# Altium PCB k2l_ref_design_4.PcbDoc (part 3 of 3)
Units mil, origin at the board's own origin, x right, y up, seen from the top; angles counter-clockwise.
Board outline 8000 x 6000 mil, 2 copper layers (Top Layer, Bottom Layer), stack 62 mil thick; 620 components, 466 nets, 2754 pads, 0 vias.
Unrouted connection lines stored in the file: 183.
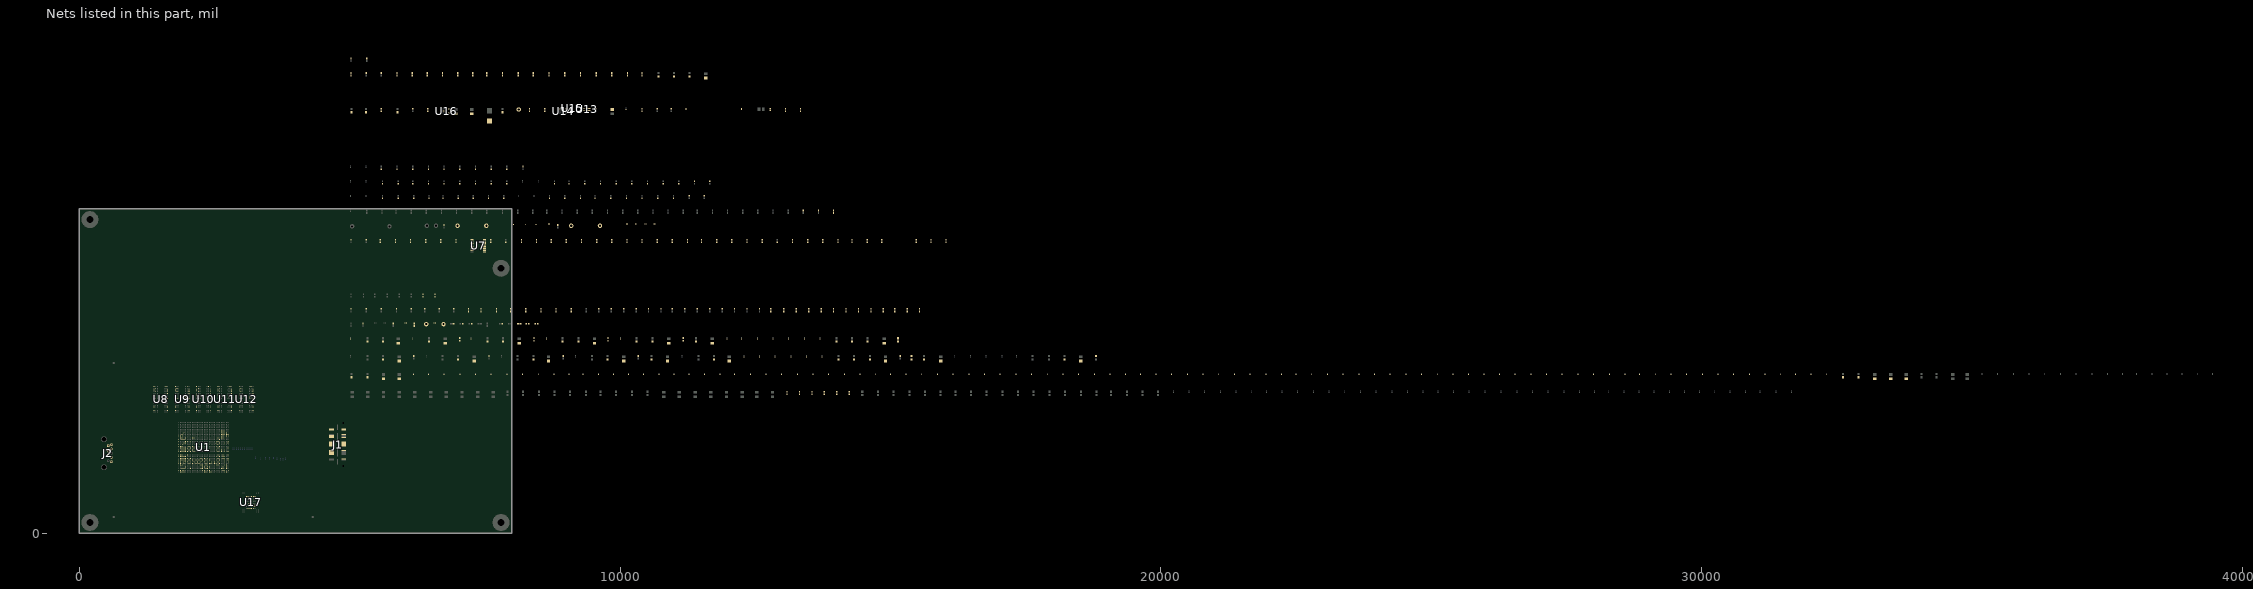
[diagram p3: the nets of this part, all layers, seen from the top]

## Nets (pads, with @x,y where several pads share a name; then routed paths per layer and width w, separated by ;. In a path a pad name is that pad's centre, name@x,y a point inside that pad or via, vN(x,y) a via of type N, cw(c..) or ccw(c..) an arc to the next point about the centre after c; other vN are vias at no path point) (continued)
K2L_DVDD1V8: C435.1 C436.1 C437.1 C438.1 C441.1 C442.1 C451.1 C452.1 C453.1 C454.1 C457.1 C458.1 C461.1 C462.1 C465.1 C466.1 C469.1 C470.1 C503.1 C573.1 C574.1 C575.1 C576.1 L20.2 L21.2 L22.2 L23.2 L24.2 L25.2 L26.2 R71.2 R72.2 R73.2 R74.2 R75.2 R76.2 R77.2 R78.2 R79.2 R80.2 R81.2 R82.2 R83.2 R84.2 R99.2 R100.2 R101.2 R102.2 R103.2 R104.2 R105.2 R106.2 R115.2 R116.2 R117.2 R123.2 R213.2 R215.2 R216.2 U1.AA23 U1.AA25 U1.AA28 U1.AB2 U1.AB6 U1.AB8 U1.AB24 U1.AC7 U1.AC9 U1.AC11 U1.AC23 U1.AC25 U1.AD4 U1.AD6 U1.AD8 U1.AD10 U1.AD24 U1.AD28 U1.AE7 U1.AE9 U1.AE11 U1.AE25 U1.AG5 U1.AH8 U1.AJ1 U1.AJ30 U1.AK2 U1.AK29 U1.J29 U1.K24 U1.L25 U1.M24 U1.N25 U1.N28 U1.P24 U1.R7 U1.R23 U1.R25 U1.T6 U1.T8 U1.T24 U1.U7 U1.U23 U1.U28 U1.V6 U1.V24 U1.W3 U1.W7 U1.W23 U1.W25 U1.Y6 U1.Y24 U7.20 U17.D3 U17.G4 U17.H8 U17.J6
K2L_DVDD1V35: C504.1 C508.1 C509.1 C510.1 C511.1 C512.1 C513.1 C514.1 C515.1 C516.1 C519.1 C520.1 C521.1 C522.1 C523.1 C524.1 C525.1 C526.1 C527.1 C530.1 C531.1 C532.1 C533.1 C534.1 C535.1 C536.1 C537.1 C538.1 C541.1 C542.1 C543.1 C544.1 C545.1 C546.1 C547.1 C548.1 C549.1 C552.1 C553.1 C554.1 C555.1 C556.1 C557.1 C558.1 C559.1 C560.1 U8.A1 U8.A8 U8.B2 U8.C1 U8.C9 U8.D2 U8.D9 U8.E9 U8.F1 U8.G7 U8.H2 U8.H9 U8.K2 U8.K8 U8.N1 U8.N9 U8.R1 U8.R9 U9.A1 U9.A8 U9.B2 U9.C1 U9.C9 U9.D2 U9.D9 U9.E9 U9.F1 U9.G7 U9.H2 U9.H9 U9.K2 U9.K8 U9.N1 U9.N9 U9.R1 U9.R9 U10.A1 U10.A8 U10.B2 U10.C1 U10.C9 U10.D2 U10.D9 U10.E9 U10.F1 U10.G7 U10.H2 U10.H9 U10.K2 U10.K8 U10.N1 U10.N9 U10.R1 U10.R9 U11.A1 U11.A8 U11.B2 U11.C1 U11.C9 U11.D2 U11.D9 U11.E9 U11.F1 U11.G7 U11.H2 U11.H9 U11.K2 U11.K8 U11.N1 U11.N9 U11.R1 U11.R9 U12.A1 U12.A8 U12.B2 U12.C1 U12.C9 U12.D2 U12.D9 U12.E9 U12.F1 U12.G7 U12.H2 U12.H9 U12.K2 U12.K8 U12.N1 U12.N9 U12.R1 U12.R9
K2L_EMIFA11: R217.1 U17.C4
K2L_EMIFA11_RS: R217.2 U1.AD30
K2L_EMIFA12: R218.1 U17.D5
K2L_EMIFA12_RS: R218.2 U1.V28
K2L_EMIFBE0Z: R214.1
K2L_EMIFBE0Z_RS: R214.2 U1.AB30
K2L_EMIFCE0Z: R201.1 U17.C6
K2L_EMIFD00: R202.2 U17.H4
K2L_EMIFD00_RS: R202.1 U1.U26
K2L_EMIFD01: R203.2 U17.J4
K2L_EMIFD01_RS: R203.1 U1.AB28
K2L_EMIFD02: R204.2 U17.K4
K2L_EMIFD02_RS: R204.1 U1.W27
K2L_EMIFD03: R205.2 U17.K5
K2L_EMIFD03_RS: R205.1 U1.AC28
K2L_EMIFD04: R206.2 U17.K6
K2L_EMIFD04_RS: R206.1 U1.Y27
K2L_EMIFD05: R208.2 U17.J7
K2L_EMIFD05_RS: R208.1 U1.AB27
K2L_EMIFD06: R210.2 U17.K7
K2L_EMIFD06_RS: R210.1 U1.AA27
K2L_EMIFD07: R212.2 U17.J8
K2L_EMIFD07_RS: R212.1 U1.V26
K2L_EMIFOEZ: R207.1 U17.D4
K2L_EMIFOEZ_RS: R207.2 U1.T30
K2L_EMIFRNW: R211.1
K2L_EMIFRNW_RS: R211.2 U1.M30
K2L_EMIFWAIT0: R213.1 U1.AC30 U1.Y30 U17.C8
K2L_EMIFWEZ: R209.1 U17.C7
K2L_EMIFWEZ_RS: R209.2 U1.V30
K2L_GPIO0: R106.1 R114.2 U1.G26
K2L_GPIO1: R84.1 R98.2 U1.F27
K2L_GPIO2: R83.1 R97.2 U1.F26
K2L_GPIO3: R82.1 R96.2 U1.G29
K2L_GPIO4: R81.1 R95.2 U1.F28
K2L_GPIO5: R80.1 R94.2 U1.G27
K2L_GPIO6: R79.1 R93.2 U1.H30
K2L_GPIO7: R78.1 R92.2 U1.J26
K2L_GPIO8: R77.1 R91.2 U1.H26
K2L_GPIO9: R76.1 R90.2 U1.H29
K2L_GPIO10: R75.1 R89.2 U1.J27
K2L_GPIO11: R74.1 R88.2 U1.H28
K2L_GPIO12: R73.1 R87.2 U1.G28
K2L_GPIO13: R72.1 R86.2 U1.H27
K2L_GPIO14: R105.1 R113.2 U1.J30
K2L_GPIO15: R104.1 R112.2 U1.K27
K2L_GPIO16: R103.1 R111.2 U1.K26
K2L_GPIO17: U1.W2
K2L_GPIO18: U1.Y1
K2L_GPIO19: U1.V3
K2L_GPIO20: U1.W1
K2L_GPIO21: U1.V1
K2L_GPIO22: U1.V2
K2L_GPIO23: U1.U4
K2L_GPIO24: U1.V5
K2L_GPIO26: U1.V4
K2L_GPIO27: U1.U1
K2L_GPIO28: U1.T3
K2L_GPIO29: U1.U3
K2L_GPIO30: U1.T5
K2L_GPIO31: U1.U5
K2L_GPIO32: U1.T4
K2L_JESD_RXN0: C6.2
K2L_JESD_RXN0_CAP: C6.1 U1.AJ19
K2L_JESD_RXN1: C8.2
K2L_JESD_RXN1_CAP: C8.1 U1.AK20
K2L_JESD_RXN2: C10.2
K2L_JESD_RXN2_CAP: C10.1 U1.AJ16
K2L_JESD_RXN3: C12.2
K2L_JESD_RXN3_CAP: C12.1 U1.AK17
K2L_JESD_RXP0: C5.2
K2L_JESD_RXP0_CAP: C5.1 U1.AJ18
K2L_JESD_RXP1: C7.2
K2L_JESD_RXP1_CAP: C7.1 U1.AK19
K2L_JESD_RXP2: C9.2
K2L_JESD_RXP2_CAP: C9.1 U1.AJ15
K2L_JESD_RXP3: C11.2
K2L_JESD_RXP3_CAP: C11.1 U1.AK16
K2L_JESD_SERDES0_REFCLKN: JESDCLK2.1 U1.AF18
K2L_JESD_SERDES0_REFCLKP: JESDCLK1.1 U1.AF17
K2L_JESD_SERDES1_REFCLKN: JESDCLK4.1 U1.AF15
K2L_JESD_SERDES1_REFCLKP: JESDCLK3.1 U1.AF14
K2L_JESD_TXN0: U1.AH17
K2L_JESD_TXN1: U1.AG18
K2L_JESD_TXN2: U1.AH14
K2L_JESD_TXN3: U1.AG15
K2L_JESD_TXP0: U1.AH18
K2L_JESD_TXP1: U1.AG19
K2L_JESD_TXP2: U1.AH15
K2L_JESD_TXP3: U1.AG16
K2L_LRESETNMIENZ: R3.1 U1.AF2
K2L_LRESETZ: R1.1 U1.AK3
K2L_MIPI_DETECTZ: J1.58 R123.1
K2L_MIPI_EMU00: J1.19 R124.1
K2L_MIPI_EMU00_RS: R124.2 U1.AC3
K2L_MIPI_EMU01: J1.21 R125.1
K2L_MIPI_EMU01_RS: R125.2 U1.AD5
K2L_MIPI_EMU02: J1.13 R127.1
K2L_MIPI_EMU02_RS: R127.2 U1.AD1
K2L_MIPI_EMU03: J1.17 R128.1
K2L_MIPI_EMU03_RS: R128.2 U1.AD2
K2L_MIPI_EMU04: J1.23 R129.1
K2L_MIPI_EMU04_RS: R129.2 U1.AE1
K2L_MIPI_EMU05: J1.25 R130.1
K2L_MIPI_EMU05_RS: R130.2 U1.AC4
K2L_MIPI_EMU06: J1.27 R131.1
K2L_MIPI_EMU06_RS: R131.2 U1.AC5
K2L_MIPI_EMU07: J1.29 R132.1
K2L_MIPI_EMU07_RS: R132.2 U1.AC2
K2L_MIPI_EMU08: J1.31 R133.1
K2L_MIPI_EMU08_RS: R133.2 U1.AC1
K2L_MIPI_EMU09: J1.33 R134.1
K2L_MIPI_EMU09_RS: R134.2 U1.AB4
K2L_MIPI_EMU10: J1.35 R135.1
K2L_MIPI_EMU10_RS: R135.2 U1.AB5
K2L_MIPI_EMU11: J1.37 R136.1
K2L_MIPI_EMU11_RS: R136.2 U1.AB3
K2L_MIPI_EMU12: J1.39 R137.1
K2L_MIPI_EMU12_RS: R137.2 U1.AA1
K2L_MIPI_EMU13: J1.41 R138.1
K2L_MIPI_EMU13_RS: R138.2 U1.AA4
K2L_MIPI_EMU14: J1.43 R139.1
K2L_MIPI_EMU14_RS: R139.2 U1.AA2
K2L_MIPI_EMU15: J1.45 R140.1
K2L_MIPI_EMU15_RS: R140.2 U1.AA3
K2L_MIPI_EMU16: J1.47 R141.1
K2L_MIPI_EMU16_RS: R141.2 U1.AA5
K2L_MIPI_EMU17: J1.49 R142.1
K2L_MIPI_EMU17_RS: R142.2 U1.Y3
K2L_MIPI_EMU18: J1.51 R143.1
K2L_MIPI_EMU18_RS: R143.2 U1.Y2
K2L_MIPI_EMU19: J1.53
K2L_MIPI_EMU20: J1.55
K2L_MIPI_EMU21: J1.18
K2L_MIPI_EMU22: J1.20
K2L_MIPI_EMU23: J1.22
K2L_MIPI_EMU24: J1.24
K2L_MIPI_EMU25: J1.26
K2L_MIPI_EMU26: J1.28
K2L_MIPI_EMU27: J1.30
K2L_MIPI_EMU28: J1.32
K2L_MIPI_EMU29: J1.34
K2L_MIPI_EMU30: J1.36
K2L_MIPI_EMU31: J1.38
K2L_MIPI_EMU32: J1.40
K2L_MIPI_EMU33: J1.42
K2L_MIPI_TCK: R148.2 U1.AJ3
K2L_MIPI_TCK_BUFF: R119.1 U7.11 U7.13
K2L_MIPI_TCK_BUFF_RS: J1.3 R119.2
K2L_MIPI_TCK_RS: R148.1 U7.9
K2L_MIPI_TCKR_BUFF: J1.7 R149.2
K2L_MIPI_TCKR_BUFF_RS: R149.1 U7.7
K2L_MIPI_TDI: R147.2 U1.AJ4
K2L_MIPI_TDI_BUFF: R120.1 U7.8
K2L_MIPI_TDI_BUFF_RS: J1.5 R120.2
K2L_MIPI_TDI_RS: R147.1 U7.12
K2L_MIPI_TDO: J1.4 R146.2
K2L_MIPI_TDO_BUFF: R122.1 U7.6
K2L_MIPI_TDO_BUFF_RS: R122.2 U1.AH4
K2L_MIPI_TDO_RS: R146.1 U7.14
K2L_MIPI_TGTDETECTZ: J1.15 R126.1
K2L_MIPI_TGTRSTZ: J1.6 R115.1
K2L_MIPI_TMS: R145.2 U1.AH3
K2L_MIPI_TMS_BUFF: R118.2 U7.4
K2L_MIPI_TMS_BUFF_RS: J1.2 R118.1
K2L_MIPI_TMS_RS: R145.1 U7.16
K2L_MIPI_TRSTZ: R144.2 U1.AK4
K2L_MIPI_TRSTZ_BUFF: R121.2 U7.2
K2L_MIPI_TRSTZ_BUFF_RS: J1.8 R121.1
K2L_MIPI_TRSTZ_RS: R144.1 U7.18
K2L_MIPI_VREF_JTAG: J1.1 R116.1
K2L_NMIZ: R2.1 U1.AJ2
K2L_PCIECLKN: U1.AE20
K2L_PCIECLKP: U1.AE19
K2L_PLLLOCK: K1.1 R12.2 U1.AH29
K2L_PORZ: R6.2 U1.G4
K2L_RESETFULLZ: R7.2 U1.AE2
K2L_RESETSTATZ: R4.2 U1.AE4
K2L_RESETZ: R8.2 U1.AF3
K2L_SCL1: R16.1 U1.L3
K2L_SDA1: R15.1 U1.M5
K2L_SERDES0_REF: R23.2 U1.AE17
K2L_SERDES1_REF: R24.2 U1.AE13
K2L_SGMIICLKN: U1.AF24
K2L_SGMIICLKP: U1.AF23
K2L_SYSCLKN: C2.2
K2L_SYSCLKN_CS: C2.1 U1.AG29
K2L_SYSCLKOUT: K2.1 R11.2
K2L_SYSCLKOUT_RS: R11.1 U1.AF28
K2L_SYSCLKP: C1.2
K2L_SYSCLKP_CS: C1.1 U1.AF29
K2L_TIMI0: R100.1 R108.2 U1.J2
K2L_TIMI1: R99.1 R107.2 U1.J1
K2L_TIMO0: R102.1 R110.2 U1.H3
K2L_TIMO1: R101.1 R109.2 U1.J3
K2L_UART0_CTS: U1.L4
K2L_UART0_RTS: U1.K2
K2L_UART0_RXD: U1.K5
K2L_UART0_TXD: U1.K3
K2L_USBCLKN: 
K2L_USBCLKP: 
K2L_USBCLKP_CS: R188.1 R189.1 R190.1 R190.2 R191.2 R192.2 U1.P3 U1.R3
K2L_USBDM: J2.2 U1.R1 U13.2 U13.13
K2L_USBDP: J2.3 U1.P1 U13.1 U13.14
K2L_USBDRVVBUS: R198.1 U1.M6
K2L_USBDRVVBUS_INVOUT: R196.1 R200.2 U14.4 U16.4
K2L_USBDRVVBUS_RS: R198.2 R200.1 U16.2
K2L_USBRXM: J2.5 U1.T2 U13.6 U13.9
K2L_USBRXP: J2.6 U1.R2 U13.7 U13.8
K2L_USBTXM: C563.2 U1.M1
K2L_USBTXM_CS: C563.1 J2.8 U13.3 U13.12
K2L_USBTXP: C564.2 U1.L1
K2L_USBTXP_CS: C564.1 J2.9 U13.4 U13.11
K2L_USBVBUS: C566.1 R193.1 U15.A1
K2L_USBVBUS_EN: R199.2 U15.B2
K2L_USBVBUS_RS: C565.1 R193.2 U1.N4
K2L_VCNTL0: R70.1 U1.AJ27
K2L_VCNTL1: R69.1 U1.AK28
K2L_VCNTL2: R68.1 U1.AJ28
K2L_VCNTL3: R67.1 U1.AG27
K2L_VCNTL4_VCL: R66.1 U1.AH27
K2L_VCNTL5_VD: R65.1 U1.AH26
K2L_VDDAHV_1V8_FILT: C443.1 C444.1 C445.1 C446.1 C447.1 C448.1 C449.1 C450.1 L22.1 U1.AD12 U1.AD14 U1.AD16 U1.AD18 U1.AD20 U1.AD22
K2L_VDDALV_FILT: C471.1 C472.1 C473.1 C474.1 C475.1 C476.1 C477.1 C478.1 C479.1 L27.1 U1.AB14 U1.AB16 U1.AB18 U1.AC13 U1.AC15 U1.AC17 U1.AC19
K2L_VDDCMON: U1.K10
K2L_VDDTMON: U1.N23
K2L_VDDUSB: C492.1 C493.1 L30.1 U1.U9
K2L_VP_FILT: C484.1 C485.1 L28.1 U1.V8
K2L_VPH_FILT: C499.1 C500.1 L31.1 U1.T10
K2L_VPTX_FILT: C488.1 C489.1 L29.1 U1.V10
K2L_VSSCMON: U1.K9
K2L_VSSTMON: U1.M23
MCU_NAND_WP_EN#: R216.1 R220.2 U17.C3
MIPI_VREF_EMU: J1.12 R117.1
NAND_LOCKPRE: R215.1 R219.2 U17.G5
NetC504_2: C504.2 R152.2 R153.2
NetR150_2: R150.2 U7.15 U7.17
NetR151_2: R151.2 U7.1 U7.19
NetR194_2: R194.2 U1.N5
NetR195_2: R195.2 U1.M8
NetR197_1: R197.1 U14.5
NetR201_2: R201.2 U1.N30
NetR221_2: R221.2 U1.AE23
NetR222_2: R222.2 U1.AE22
SDRAM_RZQ0: R183.2 R185.2 R186.2 R187.2 U8.L8 U10.L8 U11.L8 U12.L8
SDRAM_RZQ1: R184.2 U9.L8
USB_VBUS: C570.1
USB_VBUS_5V0: C567.1 C568.1 C569.1 J2.1 K15.1 U14.1 U15.A2
VSYS_DVDD0V85: C480.1 C481.1 C482.1 C483.1 C486.1 C487.1 C490.1 C491.1 C494.1 C495.1 L27.2 L28.2 L29.2 L30.2 R188.2 R189.2
VSYS_DVDD1V8: C324.1 C325.1 C326.1 C327.1 C328.1 C329.1 C330.1 C331.1 C332.1 C333.1 C334.1 C335.1 C336.1 C337.1 C338.1 C339.1 C340.1 C341.1 C342.1 C343.1 C344.1 C345.1 C346.1 C347.1 C348.1 C349.1 C350.1 C351.1 C352.1 C353.1 C354.1 C355.1 C356.1 C357.1 C358.1 C359.1 C360.1 C361.1 C362.1 C363.1 C364.1 C365.1 C366.1 C367.1 C368.1 C369.1 C370.1 C371.1 C372.1 C373.1 C374.1 C375.1 C376.1 C377.1 C378.1 C379.1 C380.1 R1.2 R2.2 R3.2 R13.2 R15.2 R16.2 R65.2 R66.2 R67.2 R68.2 R69.2 R70.2 U16.5
VSYS_DVDD1V35: C381.1 C382.1 C383.1 C384.1 C385.1 C386.1 C387.1 C388.1 C389.1 C390.1 C391.1 C392.1 C393.1 C394.1 C395.1 C396.1 C397.1 C398.1 C399.1 C400.1 C401.1 C402.1 C403.1 C404.1 C405.1 C406.1 C407.1 C408.1 C409.1 C410.1 C411.1 C412.1 C413.1 C414.1 C415.1 C416.1 C417.1 C418.1 C419.1 C420.1 C424.1 C425.1 C426.1 C427.1
VSYS_DVDD3V3: C496.1 C497.1 C498.1 C501.1 C502.1 L31.2 U1.R9
VSYS_DVDD5V0: C571.1 C572.1 R196.2 R197.2
pads on no net: FID1.1 FID2.1 FID3.1 H1.1 H2.1 H3.1 H4.1 J1.9 J1.10 J1.11 J1.14 J1.44 J1.46 J1.48 J1.50 J1.52 J1.54 J1.56 J1.59 J1.60 J1.MH1 J1.MH2 U1.A11 U1.AA26 U1.AA30 U1.AB26 U1.AB29 U1.AC26 U1.AC27 U1.AC29 U1.AD26 U1.AD27 U1.AE3 U1.AE15 U1.AE21 U1.AE28 U1.AE29 U1.AF1 U1.AF4 U1.AF5 U1.AF6 U1.AF8 U1.AF20 U1.AF22 U1.AG1 U1.AG2 U1.AH1 U1.AH2 U1.AH28 U1.AJ12 U1.AJ13 U1.AJ29 U1.AK13 U1.AK14 U1.B14 U1.B15 U1.C12 U1.E13 U1.F1 U1.F2 U1.F3 U1.F11 U1.F14 U1.F17 U1.G2 U1.H1 U1.H25 U1.J4 U1.J5 U1.J25 U1.K4 U1.K28 U1.K29 U1.K30 U1.L5 U1.L28 U1.M2 U1.M3 U1.M4 U1.M27 U1.M29 U1.N2 U1.P26 U1.P27 U1.P28 U1.P29 U1.P30 U1.R26 U1.R27 U1.R28 U1.R29 U1.R30 U1.T26 U1.T27 U1.T28 U1.T29 U1.U27 U1.U30 U1.V27 U1.V29 U1.W5 U1.W26 U1.W28 U1.W29 U1.W30 U1.Y4 U1.Y26 U1.Y28 U1.Y29 U7.3 U7.5 U8.J1 U8.J9 U8.L1 U8.L9 U8.M7 U9.J1 U9.J9 U9.L1 U9.L9 U9.M7 U10.J1 U10.J9 U10.L1 U10.L9 U10.M7 U11.J1 U11.J9 U11.L1 U11.L9 U11.M7 U12.A2 U12.A3 U12.A7 U12.B7 U12.B8 U12.C2 U12.C3 U12.C7 U12.C8 U12.D3 U12.D7 U12.J1 U12.J9 U12.L1 U12.L9 U12.M7 U14.3 U16.1 U17.A1 U17.A2 U17.A9 U17.A10 U17.B1 U17.B9 U17.B10 U17.D6 U17.D7 U17.D8 U17.E3 U17.E4 U17.E5 U17.E6 U17.E7 U17.E8 U17.F3 U17.F4 U17.F5 U17.F6 U17.F8 U17.G3 U17.G6 U17.G7 U17.G8 U17.H3 U17.H5 U17.H6 U17.H7 U17.J3 U17.J5 U17.L1 U17.L2 U17.L9 U17.L10 U17.M1 U17.M2 U17.M9 U17.M10

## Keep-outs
Keep-Out Layer:
  text ".Layer_Name" at 577,-858.49 h60

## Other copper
Top Layer:
  text ".Layer_Name" at 577,-858.49 h60
Bottom Layer:
  text ".Layer_Name" at 577,-858.49 h60

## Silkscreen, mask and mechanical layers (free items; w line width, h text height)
Top Overlay:
  region: 2680,210 2380,210 2380,110 2680,110
  text "'.PRJ_Number'.PCB_Rev-" at 1720.47,118.11 h108.27
  text ".Layer_Name" at 577,-858.49 h60
Bottom Overlay:
  text ".Layer_Name" at 577,-858.49 h60
Top Paste:
  text ".Layer_Name" at 577,-858.49 h60
Bottom Paste:
  text ".Layer_Name" at 577,-858.49 h60
Top Solder:
  text ".Layer_Name" at 577,-858.49 h60
  text ".Layer_Name" at 577,-858.49 h60
Bottom Solder:
  text ".Layer_Name" at 577,-858.49 h60
Drill Guide:
  text ".Layer_Name" at 577,-858.49 h60
M1 Board Outline:
  the board outline again, w10
  text ".Layer_Name" at 577,-858.49 h60
M2 Board Dimensions:
  rectangle: 0,-275 125,-150
  rectangle: 125,-400 500,-275
  lines w7: 0,-275 1000,-275 ; 125,-400 125,-150 ; 250,-400 250,-150 ; 500,-400 500,-150 ; 750,-400 750,-150 ; 0,-400 1000,-400 1000,-150 0,-150 0,-400
  text ".Layer_Name" at 577,-858.49 h60
M3 3D STEP Top:
  text ".Layer_Name" at 577,-858.49 h60
M4 3D STEP Bottom:
  text ".Layer_Name" at 577,-858.49 h60
M5 Assembly Top:
  lines w10: -292,-930.17 6308,-930.17 ; -292,-726.83 6310,-726.83 ; -292,-523.5 -292,-1133.5 3713,-1133.5 6310,-1133.5 6310,-523.5 -291.5,-523.5 -291.5,-1133.5 1284,-1133.5 ; 2173,-1133.5 2173,-523.5 ; 3440,-726.83 3440,-523.5 ; 4280,-726.83 4280,-523.5 ; 4902,-1140 4902,-937.17
  text "COMPONENTS MARKED 'DNP' SHOULD NOT BE POPULATED." at 1153.5,-318.5 h60
  text "ASSEMBLY VARIANT:" at 1153,-434 h60
  text ".VariantName" at 2189,-434 h60
  text "PCB VIEWED FROM TOP SIDE" at -228.5,-655.67 h60
  text "BOARD #:" at 2248,-655.67 h60
  text ".PRJ_Number" at 2793.5,-655.67 h60
  text "REV:" at 3638,-655.67 h60
  text ".PCB_Rev" at 3929.5,-655.67 h60
  text "SVN REV:" at 4476,-655.67 h60
  text ".VersionControl_RevNumber" at 4982,-655.67 h60
  text "TID #:" at 2248,-859 h60
  text ".TID" at 2793.5,-859 h60
  text "PLOT NAME =" at -228.5,-1064.34 h60
  text ".plot_File_Name" at 577,-1064.34 h60
  text "GENERATED    :" at 2250,-1064.34 h60
  text ".Print_Date" at 3119.5,-1064.34 h60
  text ".Print_Time" at 3848.5,-1064.34 h60
  text "TEXAS INSTRUMENTS" at 5113,-1064.34 h60
M6 Assembly Bottom:
  lines w10: -292.5,-727.33 6309.5,-727.33 ; -290.5,-930.67 6309.5,-930.67 ; 1115.5,-1140.5 1115.5,-937.67 ; 1737.5,-727.33 1737.5,-524 ; 2577.5,-727.33 2577.5,-524 ; 3844.5,-1134 3844.5,-524 ; 4733.5,-1134 6309,-1134 6309,-524 -292.5,-524 -292.5,-1134 2304.5,-1134 6309.5,-1134 6309.5,-524
  text "COMPONENTS MARKED 'DNP' SHOULD NOT BE POPULATED." at 6102,-318 h60
  text ".VariantName" at 5058,-434 h60
  text "ASSEMBLY VARIANT:" at 6097,-434 h60
  text ".VersionControl_RevNumber" at 1035.5,-656.17 h60
  text "SVN REV:" at 1541.5,-656.17 h60
  text ".PCB_Rev" at 2088,-656.17 h60
  text "REV:" at 2379.5,-656.17 h60
  text ".PRJ_Number" at 3224,-656.17 h60
  text "BOARD #:" at 3769.5,-656.17 h60
  text "PCB VIEWED FROM BOTTOM SIDE" at 6246,-656.17 h60
  text ".TID" at 3224,-859.5 h60
  text "TID #:" at 3769.5,-859.5 h60
  text "TEXAS INSTRUMENTS" at 904.5,-1064.84 h60
  text ".Print_Time" at 2169,-1064.84 h60
  text ".Print_Date" at 2898,-1064.84 h60
  text "GENERATED    :" at 3767.5,-1064.84 h60
  text ".plot_File_Name" at 5440.5,-1064.84 h60
  text "PLOT NAME =" at 6246,-1064.84 h60
M9 Title Sheet:
  drawing of 57 lines, arcs and shapes, not listed
  text "1" at 739.84,8036.5 h70
  text "2" at 3235.5,8036.5 h70
  text "3" at 5724.84,8036.5 h70
  text "4" at 8231.51,8036.5 h70
  text "5" at 10730.5,8036.5 h70
  text "6" at 13235.5,8036.5 h70
  text "A" at -416.5,6893.5 h70
  text "A" at 14383.5,6893.5 h70
  text "B" at -416.5,4513.5 h70
  text "B" at 14383.5,4513.5 h70
  text "C" at -416.5,2138.5 h70
  text "C" at 14383.5,2138.5 h70
  text "PROJECT TITLE:" at 11343.5,277.5 h45
  text ".PRJ_Title" at 11393.5,144.17 h70
  text "DESIGNED FOR:" at 11343.5,-23.5 h45
  text ".PRJ_Customer" at 11393.5,-163.5 h70
  text "D" at -416.5,-231.5 h70
  text "D" at 14383.5,-231.5 h70
  text "FILE NAME:" at 11343.5,-323.5 h45
  text ".PCB_File_Name_No_Path" at 11393.5,-443.5 h70
  text "Texas Instruments (TI) and/or its licensors do not warrant the accuracy or completeness of this specification" at 6374,-605.34 h45
  text "ENGINEER:" at 11343.5,-613.5 h45
  text "LAYOUT BY:" at 12848.5,-613.5 h45
  text "or any information contained therein. TI and/or its licensors do not warrant that this design will meet" at 6329.01,-718 h45
  text ".PRJ_Engineer" at 11393.5,-768.49 h70
  text ".PCB_Layout" at 12899,-768.49 h70
  text "the specifications, will be suitable for your application or fit for any particular purpose, or will operate in" at 6329.01,-830.67 h45
  text ".Layer_Name" at 577,-858.49 h60
  text "ALTIUM DESIGNER VERSION:" at 12848.5,-923.5 h45
  text "an implementation. TI and/or its licensors do not warrant that the design is production worthy. You should" at 6329.01,-943.33 h45
  text "completely validate and test your design implementation to confirm the system functionality for your application." at 6374,-1056 h45
  text ".print_Scale" at 11393.5,-1056.83 h70
  text ".Application_BuildNumber" at 12899,-1056.83 h70
  text "1" at 739.84,-1263.5 h70
  text "2" at 3235.5,-1263.5 h70
  text "3" at 5724.84,-1263.5 h70
  text "4" at 8231.51,-1263.5 h70
  text "5" at 10730.5,-1263.5 h70
  text "6" at 13235.5,-1263.5 h70
M10 Fab Notes:
  drawing of 173 lines, arcs and shapes, not listed
  text "DESIGN INFORMATION" at 12378.02,6201 h60
  text "MIN. TRACK WIDTH:" at 11733.46,6021 h60
  text "8" at 12829.7,6021 h60
  text "MIL" at 12984.46,6021 h60
  text "MIN. CLEARANCE:" at 11733.46,5889 h60
  text "0.2" at 12769.7,5889 h60
  text "mm" at 12984.46,5889 h60
  text "MIN. VIA PAD SIZE:" at 11733.46,5757 h60
  text "24" at 12799.71,5757 h60
  text "MIL" at 12984.46,5757 h60
  text "0.05mm (2MIL)" at 12428.46,5615.29 h60
  text "MINIMUM ANNULAR RING" at 11404.23,5611 h60
  text "EXTERNAL" at 13136.46,5611 h60
  text "PER" at 11604.23,5493 h60
  text "IPC-D-275 CLASS 2 LEVEL C" at 11824.23,5493 h60
  text "MIL, HOLES" at 13312.46,5380.71 h60
  text "+/-" at 12920,5380 h60
  text "+/-" at 13774,5380 h60
  text "REGISTRATION TOLERANCES:" at 11404.23,5375 h60
  text "METAL" at 12604,5375 h60
  text "5" at 13180.2,5375 h60
  text "3" at 14013.2,5375 h60
  text "MIL" at 14129.46,5375 h60
  text "+/-" at 13774,5262 h60
  text "HOLE SIZE TOLERANCE (UNLESS OTHERWISE SPECIFIED):" at 11404.23,5257 h60
  text "3" at 14013.2,5257 h60
  text "MIL" at 14129.46,5257 h60
  text "MATERIAL:" at 11329.46,5047.54 h60
  text "FR-4 High Tg" at 12315.9,4907.21 h60
  text "FR-408" at 11750.46,4898.64 h60
  text "OTHER" at 13238.46,4898.64 h60
  text "X" at 12161,4895 h60
  text "62 MIL (1.6mm) +/-10%" at 12070.56,4735.92 h60
  text "THICKNESS:" at 11404.23,4731.64 h60
  text "X" at 11942.4,4731.64 h60
  text "OTHER" at 13355.46,4731.64 h60
  text "TOLERANCE:" at 11404.23,4573.64 h60
  text "X" at 12243.53,4573.64 h60
  text "ANSI IPC-6012 TYPE 3 CLASS 2" at 12430.48,4573.64 h60
  text "OTHER +/-" at 12430.46,4417.64 h60
  text "BOW & TWIST:" at 11404.23,4260.64 h60
  text "X" at 12243.53,4260.64 h60
  text "ANSI IPC-6012 TYPE 3 CLASS 2" at 12430.48,4260.64 h60
  text "OTHER +/-" at 12430.46,4102.13 h60
  text "DRILLING:" at 11329.46,3963.64 h60
  text "REFERENCE:" at 11404.23,3846.64 h60
  text "X" at 12052.46,3846.64 h60
  text "AS SHOWN" at 12239.46,3846.64 h60
  text "X" at 12953.46,3846.64 h60
  text "NC_DRILL FILES" at 13090.46,3846.64 h60
  text "PTH COPPER THICKNESS:" at 11404.23,3688.64 h60
  text "X" at 12534.46,3688.64 h60
  text "20-30 um" at 12671.46,3688.64 h60
  text "OTHER" at 13388.46,3688.64 h60
  text "BOARD FINISH:" at 11329.46,3529.64 h60
  text "SILKSCREEN:" at 11484.68,3411.64 h60
  text "X" at 12433.46,3411.64 h60
  text "TOP" at 12559.46,3411.64 h60
  text "X" at 12943.46,3411.64 h60
  text "BOTTOM" at 13070.46,3411.64 h60
  text "SILKSCREEN COLOR:" at 11484.68,3244.64 h60
  text "X" at 12432.42,3244.64 h60
  text "WHITE" at 12559.46,3244.64 h60
  text "OTHER" at 13070.46,3244.64 h60
  text "X" at 12563.42,3085.44 h60
  text "GREEN" at 12690.46,3085.44 h60
  text "OTHER" at 13308.46,3085.44 h60
  text "SOLDER RESIST COLOR:" at 11484.68,3074.64 h60
  text "X" at 12563.42,2915.44 h60
  text "MATTE" at 12690.46,2915.44 h60
  text "SEMI-GLOSS" at 13308,2914.8 h60
  text "IMMERSION GOLD (ENIG)" at 12390.46,2726.92 h60
  text "ENEPIG" at 13728,2723.64 h60
  text "SURFACE FINISH:" at 11329.46,2722.64 h60
  text "X" at 12203.51,2722.64 h60
  text "IMM. TIN/SILVER OR EQUIV" at 11659,2565.64 h60
  text "OTHER" at 13090.46,2565.64 h60
  text "ARRAY/PANEL:" at 11329.46,2386.64 h60
  text "CUT AND TRIM PER M1 BOARD OUTLINE" at 12390.46,2382.35 h60
  text "N.C. ROUTE" at 12390.46,2230.64 h60
  text "X" at 13069.46,2230.64 h60
  text "V. SCORE" at 13256.46,2230.64 h60
  text "CERTIFICATION:" at 11329.46,2093.64 h60
  text "MATERIALS AND WORKMANSHIP FOR ALL PCBS" at 12054.46,2093.64 h60
  text "TO MEET OR EXCEED THE REQUIREMENTS OF:" at 12054.46,1995.64 h60
  text "X" at 11680.96,1859.13 h60
  text "ANSI IPC-A-600F CLASS ->" at 11819.96,1859.13 h60
  text "X" at 13459.02,1859.13 h60
  text "2" at 13577.96,1859.14 h60
  text "1" at 13262.96,1857.64 h60
  text "3" at 13931.96,1857.64 h60
  text "X" at 12495.02,1699.64 h60
  text "RoHS" at 12631.96,1699.64 h60
  text "OTHER" at 13276.36,1699.64 h60
  text "PER ORDER" at 13673.42,1699.64 h60
  text "ALL BOARDS MUST MEET OR EXCEED UL94-V0 REQUIREMENTS." at 11357,1534 h60
  text "PCB MUST BEAR THE UL94V-0 UL REGISTERED MATERIAL ID NUMBER" at 11357,1414 h60
  text "ADDITIONAL REQUIREMENTS:" at 11329.46,1240.64 h60
  text "MICROSECTION:" at 11404.23,1125.64 h60
  text "YES" at 12309.96,1125.64 h60
  text "REQUIRED" at 13171.46,969.49 h60
  text "BARE BOARD ELEC. TEST:" at 11404.23,966.64 h60
  text "NONE" at 12709.96,966.64 h60
  text "X" at 13044.46,966.64 h60
  text "PER ORDER" at 13763.46,966.64 h60
  text ".Layer_Name" at 577,-858.49 h60
M11 Gerber Information:
  lines w10: -292,-930.17 6308,-930.17 ; -292,-726.83 6310,-726.83 ; -292,-523.5 -292,-1133.5 3713,-1133.5 6310,-1133.5 6310,-523.5 -291.5,-523.5 -291.5,-1133.5 1284,-1133.5 ; 2173,-1133.5 2173,-523.5 ; 3440,-726.83 3440,-523.5 ; 4280,-726.83 4280,-523.5 ; 4902,-1140 4902,-937.17
  text "ALL ARTWORK VIEWED FROM TOP SIDE" at -228.5,-655.67 h60
  text "BOARD #:" at 2248,-655.67 h60
  text ".PRJ_Number" at 2793.5,-655.67 h60
  text "REV:" at 3638,-655.67 h60
  text ".PCB_Rev" at 3929.5,-655.67 h60
  text "SVN REV:" at 4476,-655.67 h60
  text ".VersionControl_RevNumber" at 4982,-655.67 h60
  text "LAYER NAME =" at -228.5,-858.49 h60
  text "TID #:" at 2248,-859 h60
  text ".TID" at 2793.5,-859 h60
  text "PLOT NAME =" at -228.5,-1064.34 h60
  text ".plot_File_Name" at 577,-1064.34 h60
  text "GENERATED    :" at 2250,-1064.34 h60
  text ".Print_Date" at 3119.5,-1064.34 h60
  text ".Print_Time" at 3848.5,-1064.34 h60
  text "TEXAS INSTRUMENTS" at 5113,-1064.34 h60
M12 Stackup:
  drawing of 191 lines, arcs and shapes, not listed
  text "Layer" at 9790.34,7830 h60
  text "Name" at 10200.26,7830 h60
  text "Material" at 11130,7830 h60
  text "Thickness" at 11989.77,7830 h60
  text "Constant" at 12639.6,7830 h60
  text "Board Layer Stack" at 13209.46,7830 h60
  text "1" at 9790.34,7710 h60
  text "Top Overlay" at 10200.26,7710 h60
  text "2" at 9790.34,7590 h60
  text "Top Solder" at 10200.26,7590 h60
  text "Solder Resist" at 11130,7590 h60
  text "0.40mil" at 11989.77,7590 h60
  text "3.5" at 12639.6,7590 h60
  text "3" at 9790.34,7470 h60
  text "Top Layer" at 10200.26,7470 h60
  text "Copper" at 11130,7470 h60
  text "1.40mil" at 11989.77,7470 h60
  text "4" at 9790.34,7350 h60
  text "Dielectric1" at 10200.26,7350 h60
  text "FR-4" at 11130,7350 h60
  text "59.20mil" at 11989.77,7350 h60
  text "4.8" at 12639.6,7350 h60
  text "5" at 9790.34,7230 h60
  text "Bottom Layer" at 10200.26,7230 h60
  text "Copper" at 11130,7230 h60
  text "1.40mil" at 11989.77,7230 h60
  text "6" at 9790.34,7110 h60
  text "Bottom Solder" at 10200.26,7110 h60
  text "Solder Resist" at 11130,7110 h60
  text "0.40mil" at 11989.77,7110 h60
  text "3.5" at 12639.6,7110 h60
  text "7" at 9790.34,6990 h60
  text "Bottom Overlay" at 10200.26,6990 h60
  text ".Layer_Name" at 577,-858.49 h60
M13 Component Bodies Top:
  text ".Layer_Name" at 577,-858.49 h60
M14 Component Bodies Bottom:
  text ".Layer_Name" at 577,-858.49 h60
M15 Courtyards Top:
  text ".Layer_Name" at 577,-858.49 h60
M16 Courtyards Bottom:
  text ".Layer_Name" at 577,-858.49 h60
Drill Drawing:
  circle w10: c7923.12,5632.03 r27.63
  lines w10: 7895.5,5783.97 7950.75,5783.97 7923.12,5728.72 7895.5,5783.97 ; 7895.5,5853.04 7950.75,5853.04 7950.75,5908.29 7895.5,5908.29 7895.5,5853.04 ; 7895.5,5991.17 7909.31,5991.17 7923.12,5977.36 7936.94,5991.17 7950.75,5991.17 7936.94,6004.99 7950.75,6018.8 7936.94,6018.8 7923.12,6032.61 7909.31,6018.8 7895.5,6018.8 7909.31,6004.99 7895.5,5991.17 ; 7895.5,6101.68 7923.12,6115.49 7950.75,6101.68 7936.94,6129.31 7950.75,6156.93 7923.12,6143.12 7895.5,6156.93 7909.31,6129.31 7895.5,6101.68
  lines w12: 7845.41,5567.1 11076.9,5567.1 ; 7845.41,6188.7 11076.9,6188.7 ; 8183.27,5442.78 8183.27,6313.02 ; 8515.27,5442.78 8515.27,6313.02 ; 9151.83,5442.78 9151.83,6313.02 ; 9410.97,5442.78 9410.97,6313.02 ; 9786.13,5442.78 9786.13,6313.02 ; 10510.46,5442.78 10510.46,6313.02 ; 7845.41,5442.78 11076.9,5442.78 11076.9,6313.02 7845.41,6313.02 7845.41,5442.78
  text "Symbol" at 7920,6226 h72
  text "Quantity" at 8220.57,6226 h72
  text "Finished Hole Size" at 8552.57,6226 h72
  text "Plated" at 9189.13,6226 h72
  text "Hole Type" at 9448.27,6226 h72
  text "Drill Layer Pair" at 9823.43,6226 h72
  text "Hole Tolerance" at 10547.76,6226 h72
  text "2" at 8220.57,6101.68 h60
  text "40.16mil (1.020mm)" at 8552.57,6101.68 h60
  text "NPTH" at 9189.13,6101.68 h60
  text "Round" at 9448.27,6101.68 h60
  text "Top Layer - Bottom Layer" at 9823.43,6101.68 h60
  text "9" at 8220.57,5977.36 h60
  text "27.56mil (0.700mm)" at 8552.57,5977.36 h60
  text "PTH" at 9189.13,5977.36 h60
  text "Round" at 9448.27,5977.36 h60
  text "Top Layer - Bottom Layer" at 9823.43,5977.36 h60
  text "11" at 8220.57,5853.04 h60
  text "37.99mil (0.965mm)" at 8552.57,5853.04 h60
  text "PTH" at 9189.13,5853.04 h60
  text "Round" at 9448.27,5853.04 h60
  text "Top Layer - Bottom Layer" at 9823.43,5853.04 h60
  text "2" at 8220.57,5728.72 h60
  text "90.55mil (2.300mm)" at 8552.57,5728.72 h60
  text "PTH" at 9189.13,5728.72 h60
  text "Round" at 9448.27,5728.72 h60
  text "Top Layer - Bottom Layer" at 9823.43,5728.72 h60
  text "4" at 8220.57,5604.4 h60
  text "125.98mil (3.200mm)" at 8552.57,5604.4 h60
  text "PTH" at 9189.13,5604.4 h60
  text "Round" at 9448.27,5604.4 h60
  text "Top Layer - Bottom Layer" at 9823.43,5604.4 h60
  text "28 Total" at 8220.57,5480.08 h60
  text ".Layer_Name" at 577,-858.49 h60
M17 Embedded Cavity:
  text ".Layer_Name" at 577,-858.49 h60
M18 Embedded Assembly:
  text ".Layer_Name" at 577,-858.49 h60
M19 Embedded Keepout:
  text ".Layer_Name" at 577,-858.49 h60

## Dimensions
0,-400 to 1000,-400 on M2 Board Dimensions
0,0 to 8000,0 on M2 Board Dimensions
0,0 to 0,6000 on M2 Board Dimensions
